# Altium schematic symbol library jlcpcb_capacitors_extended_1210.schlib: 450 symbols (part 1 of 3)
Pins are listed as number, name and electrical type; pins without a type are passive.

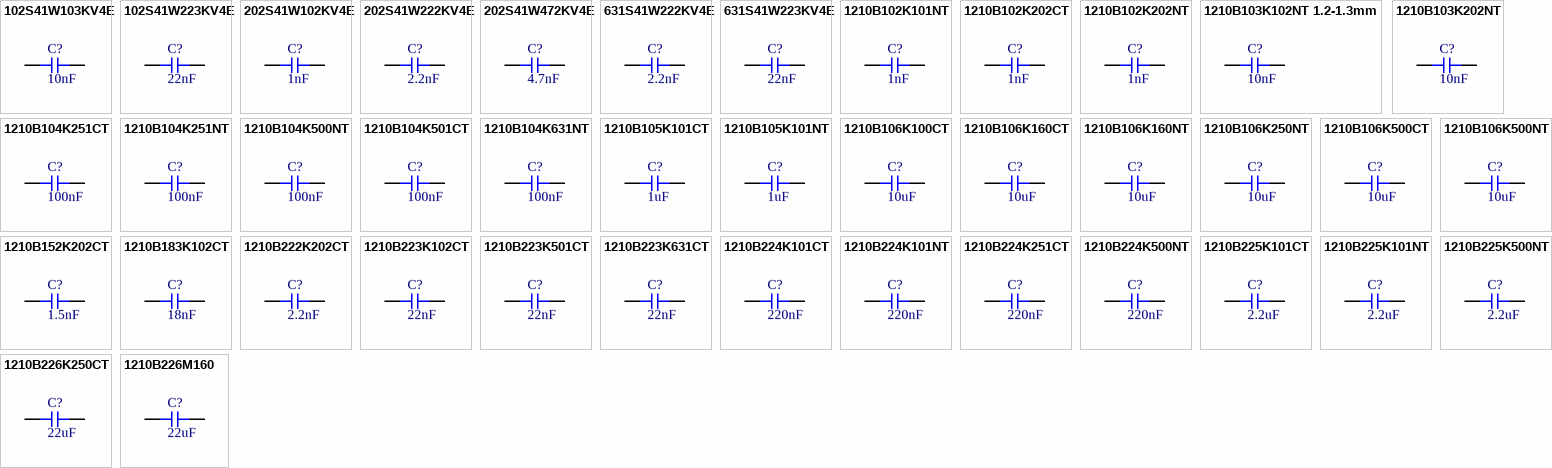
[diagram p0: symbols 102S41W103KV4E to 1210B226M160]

## 102S41W103KV4E
designator C?  Capacitance: 10nF  (hidden comment: *)
Capacitor, Ceramic (MLCC), 10nF, ±10%, 1kV, X7R, ±10%, SMD 1210; Manufacturer: Johanson Dielectrics; Manufacturer Part Number: 102S41W103KV4E
footprint CAP-1210 (1210 (3225M) Capacitor)
pins: 1, 2

## 102S41W223KV4E
designator C?  Capacitance: 22nF  (hidden comment: *)
Capacitor, Ceramic (MLCC), 22nF, ±10%, 1kV, X7R, ±10%, SMD 1210; Manufacturer: Johanson Dielectrics; Manufacturer Part Number: 102S41W223KV4E
footprint CAP-1210 (1210 (3225M) Capacitor)
pins: 1, 2

## 202S41W102KV4E
designator C?  Capacitance: 1nF  (hidden comment: *)
Capacitor, Ceramic (MLCC), 1nF, ±10%, 2kV, X7R, ±10%, SMD 1210; Manufacturer: Johanson Dielectrics; Manufacturer Part Number: 202S41W102KV4E
footprint CAP-1210 (1210 (3225M) Capacitor)
pins: 1, 2

## 202S41W222KV4E
designator C?  Capacitance: 2.2nF  (hidden comment: *)
Capacitor, Ceramic (MLCC), 2.2nF, ±10%, 2kV, X7R, ±10%, SMD 1210; Manufacturer: Johanson Dielectrics; Manufacturer Part Number: 202S41W222KV4E
footprint CAP-1210 (1210 (3225M) Capacitor)
pins: 1, 2

## 202S41W472KV4E
designator C?  Capacitance: 4.7nF  (hidden comment: *)
Capacitor, Ceramic (MLCC), 4.7nF, ±10%, 2kV, X7R, ±10%, SMD 1210; Manufacturer: Johanson Dielectrics; Manufacturer Part Number: 202S41W472KV4E
footprint CAP-1210 (1210 (3225M) Capacitor)
pins: 1, 2

## 631S41W222KV4E
designator C?  Capacitance: 2.2nF  (hidden comment: *)
Capacitor, Ceramic (MLCC), 2.2nF, ±10%, 630V, X7R, ±10%, SMD 1210; Manufacturer: Johanson Dielectrics; Manufacturer Part Number: 631S41W222KV4E
footprint CAP-1210 (1210 (3225M) Capacitor)
pins: 1, 2

## 631S41W223KV4E
designator C?  Capacitance: 22nF  (hidden comment: *)
Capacitor, Ceramic (MLCC), 22nF, ±10%, 630V, X7R, ±10%, SMD 1210; Manufacturer: Johanson Dielectrics; Manufacturer Part Number: 631S41W223KV4E
footprint CAP-1210 (1210 (3225M) Capacitor)
pins: 1, 2

## 1210B102K101NT
designator C?  Capacitance: 1nF  (hidden comment: *)
Capacitor, Ceramic (MLCC), 1nF, ±10%, 100V, X7R, ±10%, SMD 1210; Manufacturer: FH(Guangdong Fenghua Advanced Tech); Manufacturer Part Number: 1210B102K101NT
footprint CAP-1210 (1210 (3225M) Capacitor)
pins: 1, 2

## 1210B102K202CT
designator C?  Capacitance: 1nF  (hidden comment: *)
Capacitor, Ceramic (MLCC), 1nF, ±10%, 2kV, X7R, ±10%, SMD 1210; Manufacturer: Walsin Tech Corp; Manufacturer Part Number: 1210B102K202CT
footprint CAP-1210 (1210 (3225M) Capacitor)
pins: 1, 2

## 1210B102K202NT
designator C?  Capacitance: 1nF  (hidden comment: *)
Capacitor, Ceramic (MLCC), 1nF, ±10%, 2kV, ±10%, SMD 1210; Manufacturer: FH (Guangdong Fenghua Advanced Tech); Manufacturer Part Number: 1210B102K202NT
footprint CAP-1210 (1210 (3225M) Capacitor)
pins: 1, 2

## 1210B103K102NT 1.2-1.3mm
designator C?  Capacitance: 10nF  (hidden comment: *)
Capacitor, Ceramic (MLCC), 10nF, ±10%, 1kV, X7R, ±10%, SMD 1210; Manufacturer: FH(Guangdong Fenghua Advanced Tech); Manufacturer Part Number: 1210B103K102NT 1.2-1.3mm
footprint CAP-1210 (1210 (3225M) Capacitor)
pins: 1, 2

## 1210B103K202NT
designator C?  Capacitance: 10nF  (hidden comment: *)
Capacitor, Ceramic (MLCC), 10nF, ±10%, 2kV, X7R, ±10%, SMD 1210; Manufacturer: FH(Guangdong Fenghua Advanced Tech); Manufacturer Part Number: 1210B103K202NT
footprint CAP-1210 (1210 (3225M) Capacitor)
pins: 1, 2

## 1210B104K251CT
designator C?  Capacitance: 100nF  (hidden comment: *)
Capacitor, Ceramic (MLCC), 100nF, ±10%, 250V, X7R, ±10%, SMD 1210; Manufacturer: Walsin Tech Corp; Manufacturer Part Number: 1210B104K251CT
footprint CAP-1210 (1210 (3225M) Capacitor)
pins: 1, 2

## 1210B104K251NT
designator C?  Capacitance: 100nF  (hidden comment: *)
Capacitor, Ceramic (MLCC), 100nF, ±10%, 250V, X7R, ±10%, SMD 1210; Manufacturer: FH(Guangdong Fenghua Advanced Tech); Manufacturer Part Number: 1210B104K251NT
footprint CAP-1210 (1210 (3225M) Capacitor)
pins: 1, 2

## 1210B104K500NT
designator C?  Capacitance: 100nF  (hidden comment: *)
Capacitor, Ceramic (MLCC), 100nF, ±10%, 50V, X7R, ±10%, SMD 1210; Manufacturer: FH(Guangdong Fenghua Advanced Tech); Manufacturer Part Number: 1210B104K500NT
footprint CAP-1210 (1210 (3225M) Capacitor)
pins: 1, 2

## 1210B104K501CT
designator C?  Capacitance: 100nF  (hidden comment: *)
Capacitor, Ceramic (MLCC), 100nF, ±10%, 500V, X7R, ±10%, SMD 1210; Manufacturer: Walsin Tech Corp; Manufacturer Part Number: 1210B104K501CT
footprint CAP-1210 (1210 (3225M) Capacitor)
pins: 1, 2

## 1210B104K631NT
designator C?  Capacitance: 100nF  (hidden comment: *)
Capacitor, Ceramic (MLCC), 100nF, ±10%, 630V, ±10%, SMD 1210; Manufacturer: FH(Guangdong Fenghua Advanced Tech); Manufacturer Part Number: 1210B104K631NT
footprint CAP-1210 (1210 (3225M) Capacitor)
pins: 1, 2

## 1210B105K101CT
designator C?  Capacitance: 1uF  (hidden comment: *)
Capacitor, Ceramic (MLCC), 1uF, ±10%, 100V, X7R, ±10%, SMD 1210; Manufacturer: Walsin Tech Corp; Manufacturer Part Number: 1210B105K101CT
footprint CAP-1210 (1210 (3225M) Capacitor)
pins: 1, 2

## 1210B105K101NT
designator C?  Capacitance: 1uF  (hidden comment: *)
Capacitor, Ceramic (MLCC), 1uF, ±10%, 100V, X7R, ±10%, SMD 1210; Manufacturer: FH(Guangdong Fenghua Advanced Tech); Manufacturer Part Number: 1210B105K101NT
footprint CAP-1210 (1210 (3225M) Capacitor)
pins: 1, 2

## 1210B106K100CT
designator C?  Capacitance: 10uF  (hidden comment: *)
Capacitor, Ceramic (MLCC), 10uF, ±10%, 10V, X7R, ±10%, SMD 1210; Manufacturer: Walsin Tech Corp; Manufacturer Part Number: 1210B106K100CT
footprint CAP-1210 (1210 (3225M) Capacitor)
pins: 1, 2

## 1210B106K160CT
designator C?  Capacitance: 10uF  (hidden comment: *)
Capacitor, Ceramic (MLCC), 10uF, ±10%, 16V, X7R, ±10%, SMD 1210; Manufacturer: Walsin Tech Corp; Manufacturer Part Number: 1210B106K160CT
footprint CAP-1210 (1210 (3225M) Capacitor)
pins: 1, 2

## 1210B106K160NT
designator C?  Capacitance: 10uF  (hidden comment: *)
Capacitor, Ceramic (MLCC), 10uF, ±10%, 16V, X7R, ±10%, SMD 1210; Manufacturer: FH(Guangdong Fenghua Advanced Tech); Manufacturer Part Number: 1210B106K160NT
footprint CAP-1210 (1210 (3225M) Capacitor)
pins: 1, 2

## 1210B106K250NT
designator C?  Capacitance: 10uF  (hidden comment: *)
Capacitor, Ceramic (MLCC), 10uF, ±10%, 25V, X7R, ±10%, SMD 1210; Manufacturer: FH(Guangdong Fenghua Advanced Tech); Manufacturer Part Number: 1210B106K250NT
footprint CAP-1210 (1210 (3225M) Capacitor)
pins: 1, 2

## 1210B106K500CT
designator C?  Capacitance: 10uF  (hidden comment: *)
Capacitor, Ceramic (MLCC), 10uF, ±10%, 50V, X7R, ±10%, SMD 1210; Manufacturer: Walsin Tech Corp; Manufacturer Part Number: 1210B106K500CT
footprint CAP-1210 (1210 (3225M) Capacitor)
pins: 1, 2

## 1210B106K500NT
designator C?  Capacitance: 10uF  (hidden comment: *)
Capacitor, Ceramic (MLCC), 10uF, ±10%, 50V, X7R, ±10%, SMD 1210; Manufacturer: FH(Guangdong Fenghua Advanced Tech); Manufacturer Part Number: 1210B106K500NT
footprint CAP-1210 (1210 (3225M) Capacitor)
pins: 1, 2

## 1210B152K202CT
designator C?  Capacitance: 1.5nF  (hidden comment: *)
Capacitor, Ceramic (MLCC), 1.5nF, ±10%, 2kV, X7R, ±10%, SMD 1210; Manufacturer: Walsin Tech Corp; Manufacturer Part Number: 1210B152K202CT
footprint CAP-1210 (1210 (3225M) Capacitor)
pins: 1, 2

## 1210B183K102CT
designator C?  Capacitance: 18nF  (hidden comment: *)
Capacitor, Ceramic (MLCC), 18nF, ±10%, 1kV, X7R, ±10%, SMD 1210; Manufacturer: Walsin Tech Corp; Manufacturer Part Number: 1210B183K102CT
footprint CAP-1210 (1210 (3225M) Capacitor)
pins: 1, 2

## 1210B222K202CT
designator C?  Capacitance: 2.2nF  (hidden comment: *)
Capacitor, Ceramic (MLCC), 2.2nF, ±10%, 2kV, X7R, ±10%, SMD 1210; Manufacturer: Walsin Tech Corp; Manufacturer Part Number: 1210B222K202CT
footprint CAP-1210 (1210 (3225M) Capacitor)
pins: 1, 2

## 1210B223K102CT
designator C?  Capacitance: 22nF  (hidden comment: *)
Capacitor, Ceramic (MLCC), 22nF, ±10%, 1kV, X7R, ±10%, SMD 1210; Manufacturer: Walsin Tech Corp; Manufacturer Part Number: 1210B223K102CT
footprint CAP-1210 (1210 (3225M) Capacitor)
pins: 1, 2

## 1210B223K501CT
designator C?  Capacitance: 22nF  (hidden comment: *)
Capacitor, Ceramic (MLCC), 22nF, ±10%, 500V, X7R, ±10%, SMD 1210; Manufacturer: Walsin Tech Corp; Manufacturer Part Number: 1210B223K501CT
footprint CAP-1210 (1210 (3225M) Capacitor)
pins: 1, 2

## 1210B223K631CT
designator C?  Capacitance: 22nF  (hidden comment: *)
Capacitor, Ceramic (MLCC), 22nF, ±10%, 630V, X7R, ±10%, SMD 1210; Manufacturer: Walsin Tech Corp; Manufacturer Part Number: 1210B223K631CT
footprint CAP-1210 (1210 (3225M) Capacitor)
pins: 1, 2

## 1210B224K101CT
designator C?  Capacitance: 220nF  (hidden comment: *)
Capacitor, Ceramic (MLCC), 220nF, ±10%, 100V, X7R, ±10%, SMD 1210; Manufacturer: Walsin Tech Corp; Manufacturer Part Number: 1210B224K101CT
footprint CAP-1210 (1210 (3225M) Capacitor)
pins: 1, 2

## 1210B224K101NT
designator C?  Capacitance: 220nF  (hidden comment: *)
Capacitor, Ceramic (MLCC), 220nF, ±10%, 100V, X7R, ±10%, SMD 1210; Manufacturer: FH(Guangdong Fenghua Advanced Tech); Manufacturer Part Number: 1210B224K101NT
footprint CAP-1210 (1210 (3225M) Capacitor)
pins: 1, 2

## 1210B224K251CT
designator C?  Capacitance: 220nF  (hidden comment: *)
Capacitor, Ceramic (MLCC), 220nF, ±10%, 250V, X7R, ±10%, SMD 1210; Manufacturer: Walsin Tech Corp; Manufacturer Part Number: 1210B224K251CT
footprint CAP-1210 (1210 (3225M) Capacitor)
pins: 1, 2

## 1210B224K500NT
designator C?  Capacitance: 220nF  (hidden comment: *)
Capacitor, Ceramic (MLCC), 220nF, ±10%, 50V, ±10%, SMD 1210; Manufacturer: FH(Guangdong Fenghua Advanced Tech); Manufacturer Part Number: 1210B224K500NT
footprint CAP-1210 (1210 (3225M) Capacitor)
pins: 1, 2

## 1210B225K101CT
designator C?  Capacitance: 2.2uF  (hidden comment: *)
Capacitor, Ceramic (MLCC), 2.2uF, ±10%, 100V, X7R, ±10%, SMD 1210; Manufacturer: Walsin Tech Corp; Manufacturer Part Number: 1210B225K101CT
footprint CAP-1210 (1210 (3225M) Capacitor)
pins: 1, 2

## 1210B225K101NT
designator C?  Capacitance: 2.2uF  (hidden comment: *)
Capacitor, Ceramic (MLCC), 2.2uF, ±10%, 100V, X7R, ±10%, SMD 1210; Manufacturer: FH(Guangdong Fenghua Advanced Tech); Manufacturer Part Number: 1210B225K101NT
footprint CAP-1210 (1210 (3225M) Capacitor)
pins: 1, 2

## 1210B225K500NT
designator C?  Capacitance: 2.2uF  (hidden comment: *)
Capacitor, Ceramic (MLCC), 2.2uF, ±10%, 50V, X7R, ±10%, SMD 1210; Manufacturer: FH(Guangdong Fenghua Advanced Tech); Manufacturer Part Number: 1210B225K500NT
footprint CAP-1210 (1210 (3225M) Capacitor)
pins: 1, 2

## 1210B226K250CT
designator C?  Capacitance: 22uF  (hidden comment: *)
Capacitor, Ceramic (MLCC), 22uF, ±10%, 25V, X7R, ±10%, SMD 1210; Manufacturer: Walsin Tech Corp; Manufacturer Part Number: 1210B226K250CT
footprint CAP-1210 (1210 (3225M) Capacitor)
pins: 1, 2

## 1210B226M160
designator C?  Capacitance: 22uF  (hidden comment: *)
Capacitor, Ceramic (MLCC), 22uF, ±20%, 16V, X7R, ±20%, SMD 1210; Manufacturer: Walsin Tech Corp; Manufacturer Part Number: 1210B226M160
footprint CAP-1210 (1210 (3225M) Capacitor)
pins: 1, 2

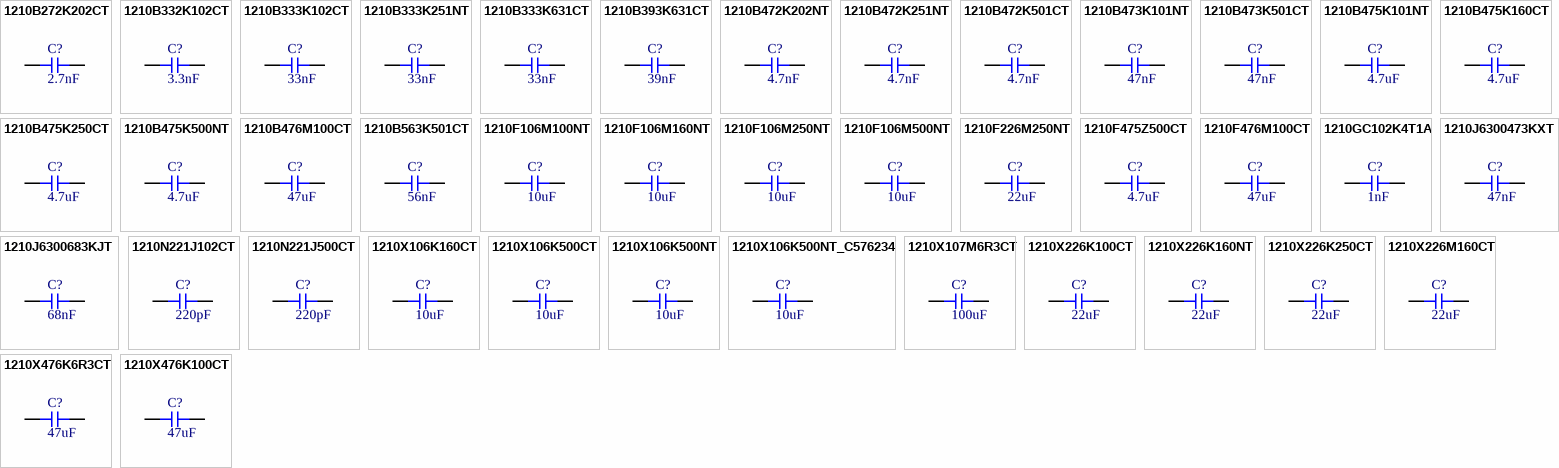
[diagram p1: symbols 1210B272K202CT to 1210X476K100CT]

## 1210B272K202CT
designator C?  Capacitance: 2.7nF  (hidden comment: *)
Capacitor, Ceramic (MLCC), 2.7nF, ±10%, 2kV, X7R, ±10%, SMD 1210; Manufacturer: Walsin Tech Corp; Manufacturer Part Number: 1210B272K202CT
footprint CAP-1210 (1210 (3225M) Capacitor)
pins: 1, 2

## 1210B332K102CT
designator C?  Capacitance: 3.3nF  (hidden comment: *)
Capacitor, Ceramic (MLCC), 3.3nF, ±10%, 1kV, X7R, ±10%, SMD 1210; Manufacturer: Walsin Tech Corp; Manufacturer Part Number: 1210B332K102CT
footprint CAP-1210 (1210 (3225M) Capacitor)
pins: 1, 2

## 1210B333K102CT
designator C?  Capacitance: 33nF  (hidden comment: *)
Capacitor, Ceramic (MLCC), 33nF, ±10%, 1kV, X7R, ±10%, SMD 1210; Manufacturer: Walsin Tech Corp; Manufacturer Part Number: 1210B333K102CT
footprint CAP-1210 (1210 (3225M) Capacitor)
pins: 1, 2

## 1210B333K251NT
designator C?  Capacitance: 33nF  (hidden comment: *)
Capacitor, Ceramic (MLCC), 33nF, ±10%, 250V, ±10%, SMD 1210; Manufacturer: FH(Guangdong Fenghua Advanced Tech); Manufacturer Part Number: 1210B333K251NT
footprint CAP-1210 (1210 (3225M) Capacitor)
pins: 1, 2

## 1210B333K631CT
designator C?  Capacitance: 33nF  (hidden comment: *)
Capacitor, Ceramic (MLCC), 33nF, ±10%, 630V, X7R, ±10%, SMD 1210; Manufacturer: Walsin Tech Corp; Manufacturer Part Number: 1210B333K631CT
footprint CAP-1210 (1210 (3225M) Capacitor)
pins: 1, 2

## 1210B393K631CT
designator C?  Capacitance: 39nF  (hidden comment: *)
Capacitor, Ceramic (MLCC), 39nF, ±10%, 630V, X7R, ±10%, SMD 1210; Manufacturer: Walsin Tech Corp; Manufacturer Part Number: 1210B393K631CT
footprint CAP-1210 (1210 (3225M) Capacitor)
pins: 1, 2

## 1210B472K202NT
designator C?  Capacitance: 4.7nF  (hidden comment: *)
Capacitor, Ceramic (MLCC), 4.7nF, ±10%, 2kV, X7R, ±10%, SMD 1210; Manufacturer: FH(Guangdong Fenghua Advanced Tech); Manufacturer Part Number: 1210B472K202NT
footprint CAP-1210 (1210 (3225M) Capacitor)
pins: 1, 2

## 1210B472K251NT
designator C?  Capacitance: 4.7nF  (hidden comment: *)
Capacitor, Ceramic (MLCC), 4.7nF, ±10%, 250V, X7R, ±10%, SMD 1210; Manufacturer: FH(Guangdong Fenghua Advanced Tech); Manufacturer Part Number: 1210B472K251NT
footprint CAP-1210 (1210 (3225M) Capacitor)
pins: 1, 2

## 1210B472K501CT
designator C?  Capacitance: 4.7nF  (hidden comment: *)
Capacitor, Ceramic (MLCC), 4.7nF, ±10%, 500V, X7R, ±10%, SMD 1210; Manufacturer: Walsin Tech Corp; Manufacturer Part Number: 1210B472K501CT
footprint CAP-1210 (1210 (3225M) Capacitor)
pins: 1, 2

## 1210B473K101NT
designator C?  Capacitance: 47nF  (hidden comment: *)
Capacitor, Ceramic (MLCC), 47nF, ±10%, 100V, X7R, ±10%, SMD 1210; Manufacturer: FH(Guangdong Fenghua Advanced Tech); Manufacturer Part Number: 1210B473K101NT
footprint CAP-1210 (1210 (3225M) Capacitor)
pins: 1, 2

## 1210B473K501CT
designator C?  Capacitance: 47nF  (hidden comment: *)
Capacitor, Ceramic (MLCC), 47nF, ±10%, 500V, X7R, ±10%, SMD 1210; Manufacturer: Walsin Tech Corp; Manufacturer Part Number: 1210B473K501CT
footprint CAP-1210 (1210 (3225M) Capacitor)
pins: 1, 2

## 1210B475K101NT
designator C?  Capacitance: 4.7uF  (hidden comment: *)
Capacitor, Ceramic (MLCC), 4.7uF, ±10%, 100V, ±10%, SMD 1210; Manufacturer: FH(Guangdong Fenghua Advanced Tech); Manufacturer Part Number: 1210B475K101NT
footprint CAP-1210 (1210 (3225M) Capacitor)
pins: 1, 2

## 1210B475K160CT
designator C?  Capacitance: 4.7uF  (hidden comment: *)
Capacitor, Ceramic (MLCC), 4.7uF, ±10%, 16V, X7R, ±10%, SMD 1210; Manufacturer: Walsin Tech Corp; Manufacturer Part Number: 1210B475K160CT
footprint CAP-1210 (1210 (3225M) Capacitor)
pins: 1, 2

## 1210B475K250CT
designator C?  Capacitance: 4.7uF  (hidden comment: *)
Capacitor, Ceramic (MLCC), 4.7uF, ±10%, 25V, X7R, ±10%, SMD 1210; Manufacturer: Walsin Tech Corp; Manufacturer Part Number: 1210B475K250CT
footprint CAP-1210 (1210 (3225M) Capacitor)
pins: 1, 2

## 1210B475K500NT
designator C?  Capacitance: 4.7uF  (hidden comment: *)
Capacitor, Ceramic (MLCC), 4.7uF, ±10%, 50V, X7R, ±10%, SMD 1210; Manufacturer: FH(Guangdong Fenghua Advanced Tech); Manufacturer Part Number: 1210B475K500NT
footprint CAP-1210 (1210 (3225M) Capacitor)
pins: 1, 2

## 1210B476M100CT
designator C?  Capacitance: 47uF  (hidden comment: *)
Capacitor, Ceramic (MLCC), 47uF, ±20%, 10V, X7R, ±20%, SMD 1210; Manufacturer: Walsin Tech Corp; Manufacturer Part Number: 1210B476M100CT
footprint CAP-1210 (1210 (3225M) Capacitor)
pins: 1, 2

## 1210B563K501CT
designator C?  Capacitance: 56nF  (hidden comment: *)
Capacitor, Ceramic (MLCC), 56nF, ±10%, 500V, X7R, ±10%, SMD 1210; Manufacturer: Walsin Tech Corp; Manufacturer Part Number: 1210B563K501CT
footprint CAP-1210 (1210 (3225M) Capacitor)
pins: 1, 2

## 1210F106M100NT
designator C?  Capacitance: 10uF  (hidden comment: *)
Capacitor, Ceramic (MLCC), 10uF, ±20%, 10V, ±20%, SMD 1210; Manufacturer: FH(Guangdong Fenghua Advanced Tech); Manufacturer Part Number: 1210F106M100NT
footprint CAP-1210 (1210 (3225M) Capacitor)
pins: 1, 2

## 1210F106M160NT
designator C?  Capacitance: 10uF  (hidden comment: *)
Capacitor, Ceramic (MLCC), 10uF, ±20%, 16V, Y5V, ±20%, SMD 1210; Manufacturer: FH(Guangdong Fenghua Advanced Tech); Manufacturer Part Number: 1210F106M160NT
footprint CAP-1210 (1210 (3225M) Capacitor)
pins: 1, 2

## 1210F106M250NT
designator C?  Capacitance: 10uF  (hidden comment: *)
Capacitor, Ceramic (MLCC), 10uF, ±20%, 25V, Y5V, ±20%, SMD 1210; Manufacturer: FH(Guangdong Fenghua Advanced Tech); Manufacturer Part Number: 1210F106M250NT
footprint CAP-1210 (1210 (3225M) Capacitor)
pins: 1, 2

## 1210F106M500NT
designator C?  Capacitance: 10uF  (hidden comment: *)
Capacitor, Ceramic (MLCC), 10uF, ±20%, 50V, Y5V, ±20%, SMD 1210; Manufacturer: FH(Guangdong Fenghua Advanced Tech); Manufacturer Part Number: 1210F106M500NT
footprint CAP-1210 (1210 (3225M) Capacitor)
pins: 1, 2

## 1210F226M250NT
designator C?  Capacitance: 22uF  (hidden comment: *)
Capacitor, Ceramic (MLCC), 22uF, ±20%, 25V, Y5V, ±20%, SMD 1210; Manufacturer: FH(Guangdong Fenghua Advanced Tech); Manufacturer Part Number: 1210F226M250NT
footprint CAP-1210 (1210 (3225M) Capacitor)
pins: 1, 2

## 1210F475Z500CT
designator C?  Capacitance: 4.7uF  (hidden comment: *)
Capacitor, Ceramic (MLCC), 4.7uF, 50V, Y5V, SMD 1210; Manufacturer: Walsin Tech Corp; Manufacturer Part Number: 1210F475Z500CT; Temperature Rating: -20%~+80%
footprint CAP-1210 (1210 (3225M) Capacitor)
pins: 1, 2

## 1210F476M100CT
designator C?  Capacitance: 47uF  (hidden comment: *)
Capacitor, Ceramic (MLCC), 47uF, ±20%, 10V, Y5V, ±20%, SMD 1210; Manufacturer: Walsin Tech Corp; Manufacturer Part Number: 1210F476M100CT
footprint CAP-1210 (1210 (3225M) Capacitor)
pins: 1, 2

## 1210GC102K4T1A
designator C?  Capacitance: 1nF  (hidden comment: *)
Capacitor, Ceramic (MLCC), 1nF, ±10%, 2kV, X7R, ±10%, SMD 1210; Manufacturer: AVX; Manufacturer Part Number: 1210GC102K4T1A
footprint CAP-1210 (1210 (3225M) Capacitor)
pins: 1, 2

## 1210J6300473KXT
designator C?  Capacitance: 47nF  (hidden comment: *)
Capacitor, Ceramic (MLCC), 47nF, ±10%, 630V, X7R, ±10%, SMD 1210; Manufacturer: Knowles; Manufacturer Part Number: 1210J6300473KXT
footprint CAP-1210 (1210 (3225M) Capacitor)
pins: 1, 2

## 1210J6300683KJT
designator C?  Capacitance: 68nF  (hidden comment: *)
Capacitor, Ceramic (MLCC), 68nF, ±10%, 630V, X7R, ±10%, SMD 1210; Manufacturer: Knowles; Manufacturer Part Number: 1210J6300683KJT
footprint CAP-1210 (1210 (3225M) Capacitor)
pins: 1, 2

## 1210N221J102CT
designator C?  Capacitance: 220pF  (hidden comment: *)
Capacitor, Ceramic (MLCC), 220pF, ±5%, 1kV, NP0, ±5%, SMD 1210; Manufacturer: Walsin Tech Corp; Manufacturer Part Number: 1210N221J102CT
footprint CAP-1210 (1210 (3225M) Capacitor)
pins: 1, 2

## 1210N221J500CT
designator C?  Capacitance: 220pF  (hidden comment: *)
Capacitor, Ceramic (MLCC), 220pF, ±5%, 50V, NP0, ±5%, SMD 1210; Manufacturer: Walsin Tech Corp; Manufacturer Part Number: 1210N221J500CT
footprint CAP-1210 (1210 (3225M) Capacitor)
pins: 1, 2

## 1210X106K160CT
designator C?  Capacitance: 10uF  (hidden comment: *)
Capacitor, Ceramic (MLCC), 10uF, ±10%, 16V, X5R, ±10%, SMD 1210; Manufacturer: Walsin Tech Corp; Manufacturer Part Number: 1210X106K160CT
footprint CAP-1210 (1210 (3225M) Capacitor)
pins: 1, 2

## 1210X106K500CT
designator C?  Capacitance: 10uF  (hidden comment: *)
Capacitor, Ceramic (MLCC), 10uF, ±10%, 50V, X5R, ±10%, SMD 1210; Manufacturer: Walsin Tech Corp; Manufacturer Part Number: 1210X106K500CT
footprint CAP-1210 (1210 (3225M) Capacitor)
pins: 1, 2

## 1210X106K500NT
designator C?  Capacitance: 10uF  (hidden comment: *)
Capacitor, Ceramic (MLCC), 10uF, ±10%, 50V, X5R, ±10%, SMD 1210; Manufacturer: FH(Guangdong Fenghua Advanced Tech); Manufacturer Part Number: 1210X106K500NT
footprint CAP-1210 (1210 (3225M) Capacitor)
pins: 1, 2

## 1210X106K500NT_C576234
designator C?  Capacitance: 10uF  (hidden comment: *)
Capacitor, Ceramic (MLCC), 10uF, ±10%, 50V, X5R, ±10%, SMD 1210; Manufacturer: FH(Guangdong Fenghua Advanced Tech); Manufacturer Part Number: 1210X106K500NT
footprint CAP-1210 (1210 (3225M) Capacitor)
pins: 1, 2

## 1210X107M6R3CT
designator C?  Capacitance: 100uF  (hidden comment: *)
Capacitor, Ceramic (MLCC), 100uF, ±20%, 6.3V, X5R, ±20%, SMD 1210; Manufacturer: Walsin Tech Corp; Manufacturer Part Number: 1210X107M6R3CT
footprint CAP-1210 (1210 (3225M) Capacitor)
pins: 1, 2

## 1210X226K100CT
designator C?  Capacitance: 22uF  (hidden comment: *)
Capacitor, Ceramic (MLCC), 22uF, ±10%, 10V, X5R, ±10%, SMD 1210; Manufacturer: Walsin Tech Corp; Manufacturer Part Number: 1210X226K100CT
footprint CAP-1210 (1210 (3225M) Capacitor)
pins: 1, 2

## 1210X226K160NT
designator C?  Capacitance: 22uF  (hidden comment: *)
Capacitor, Ceramic (MLCC), 22uF, ±10%, 16V, X5R, ±10%, SMD 1210; Manufacturer: FH(Guangdong Fenghua Advanced Tech); Manufacturer Part Number: 1210X226K160NT
footprint CAP-1210 (1210 (3225M) Capacitor)
pins: 1, 2

## 1210X226K250CT
designator C?  Capacitance: 22uF  (hidden comment: *)
Capacitor, Ceramic (MLCC), 22uF, ±10%, 25V, X5R, ±10%, SMD 1210; Manufacturer: Walsin Tech Corp; Manufacturer Part Number: 1210X226K250CT
footprint CAP-1210 (1210 (3225M) Capacitor)
pins: 1, 2

## 1210X226M160CT
designator C?  Capacitance: 22uF  (hidden comment: *)
Capacitor, Ceramic (MLCC), 22uF, ±20%, 16V, X5R, ±20%, SMD 1210; Manufacturer: Walsin Tech Corp; Manufacturer Part Number: 1210X226M160CT
footprint CAP-1210 (1210 (3225M) Capacitor)
pins: 1, 2

## 1210X476K6R3CT
designator C?  Capacitance: 47uF  (hidden comment: *)
Capacitor, Ceramic (MLCC), 47uF, ±10%, 6.3V, X5R, ±10%, SMD 1210; Manufacturer: Walsin Tech Corp; Manufacturer Part Number: 1210X476K6R3CT
footprint CAP-1210 (1210 (3225M) Capacitor)
pins: 1, 2

## 1210X476K100CT
designator C?  Capacitance: 47uF  (hidden comment: *)
Capacitor, Ceramic (MLCC), 47uF, ±10%, 10V, X5R, ±10%, SMD 1210; Manufacturer: Walsin Tech Corp; Manufacturer Part Number: 1210X476K100CT
footprint CAP-1210 (1210 (3225M) Capacitor)
pins: 1, 2

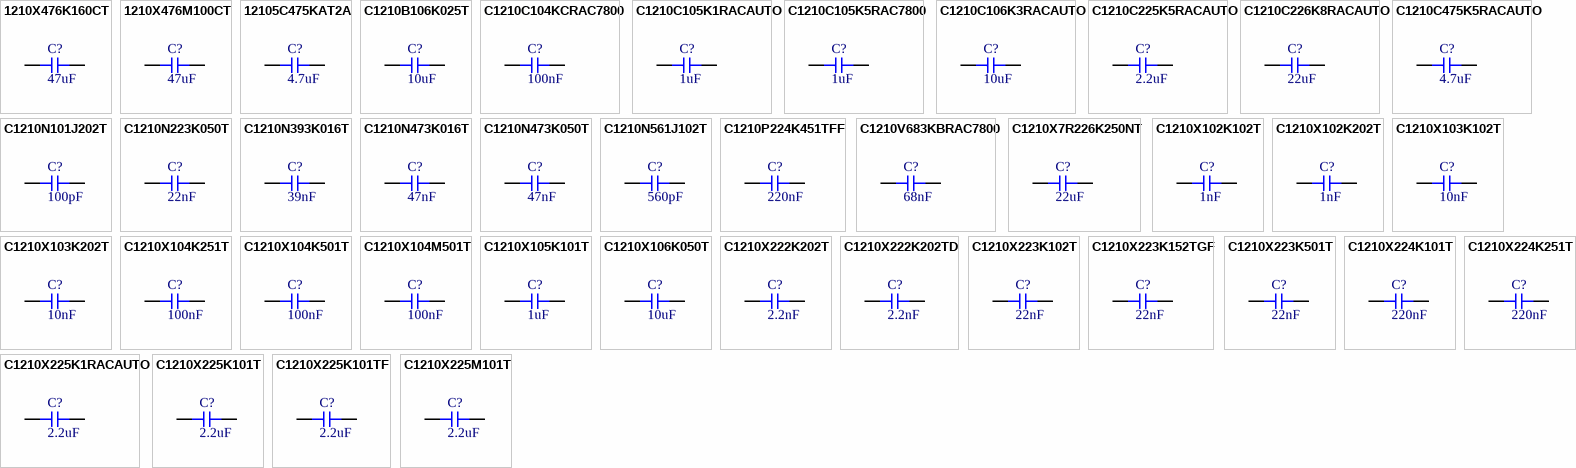
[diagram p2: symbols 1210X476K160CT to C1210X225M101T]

## 1210X476K160CT
designator C?  Capacitance: 47uF  (hidden comment: *)
Capacitor, Ceramic (MLCC), 47uF, ±10%, 16V, X5R, ±10%, SMD 1210; Manufacturer: Walsin Tech Corp; Manufacturer Part Number: 1210X476K160CT
footprint CAP-1210 (1210 (3225M) Capacitor)
pins: 1, 2

## 1210X476M100CT
designator C?  Capacitance: 47uF  (hidden comment: *)
Capacitor, Ceramic (MLCC), 47uF, ±20%, 10V, X5R, ±20%, SMD 1210; Manufacturer: Walsin Tech Corp; Manufacturer Part Number: 1210X476M100CT
footprint CAP-1210 (1210 (3225M) Capacitor)
pins: 1, 2

## 12105C475KAT2A
designator C?  Capacitance: 4.7uF  (hidden comment: *)
Capacitor, Ceramic (MLCC), 4.7uF, ±10%, 50V, X7R, ±10%, SMD 1210; Manufacturer: AVX; Manufacturer Part Number: 12105C475KAT2A
footprint CAP-1210 (1210 (3225M) Capacitor)
pins: 1, 2

## C1210B106K025T
designator C?  Capacitance: 10uF  (hidden comment: *)
Capacitor, Ceramic (MLCC), 10uF, ±10%, 25V, X5R, ±10%, SMD 1210; Manufacturer: IHHEC(HOLY STONE ENTERPRISE CO., LTD); Manufacturer Part Number: C1210B106K025T
footprint CAP-1210 (1210 (3225M) Capacitor)
pins: 1, 2

## C1210C104KCRAC7800
designator C?  Capacitance: 100nF  (hidden comment: *)
Capacitor, Ceramic (MLCC), 100nF, ±10%, 500V, X7R, ±10%, SMD 1210; Manufacturer: KEMET; Manufacturer Part Number: C1210C104KCRAC7800
footprint CAP-1210 (1210 (3225M) Capacitor)
pins: 1, 2

## C1210C105K1RACAUTO
designator C?  Capacitance: 1uF  (hidden comment: *)
Capacitor, Ceramic (MLCC), 1uF, ±10%, 100V, X7R, ±10%, SMD 1210; Manufacturer: KEMET; Manufacturer Part Number: C1210C105K1RACAUTO
footprint CAP-1210 (1210 (3225M) Capacitor)
pins: 1, 2

## C1210C105K5RAC7800
designator C?  Capacitance: 1uF  (hidden comment: *)
Capacitor, Ceramic (MLCC), 1uF, ±10%, 50V, X7R, ±10%, SMD 1210; Manufacturer: KEMET; Manufacturer Part Number: C1210C105K5RAC7800
footprint CAP-1210 (1210 (3225M) Capacitor)
pins: 1, 2

## C1210C106K3RACAUTO
designator C?  Capacitance: 10uF  (hidden comment: *)
Capacitor, Ceramic (MLCC), 10uF, ±10%, 25V, X7R, ±10%, SMD 1210; Manufacturer: KEMET; Manufacturer Part Number: C1210C106K3RACAUTO
footprint CAP-1210 (1210 (3225M) Capacitor)
pins: 1, 2

## C1210C225K5RACAUTO
designator C?  Capacitance: 2.2uF  (hidden comment: *)
Capacitor, Ceramic (MLCC), 2.2uF, ±10%, 50V, X7R, ±10%, SMD 1210; Manufacturer: KEMET; Manufacturer Part Number: C1210C225K5RACAUTO
footprint CAP-1210 (1210 (3225M) Capacitor)
pins: 1, 2

## C1210C226K8RACAUTO
designator C?  Capacitance: 22uF  (hidden comment: *)
Capacitor, Ceramic (MLCC), 22uF, ±10%, 10V, X7R, ±10%, SMD 1210; Manufacturer: KEMET; Manufacturer Part Number: C1210C226K8RACAUTO
footprint CAP-1210 (1210 (3225M) Capacitor)
pins: 1, 2

## C1210C475K5RACAUTO
designator C?  Capacitance: 4.7uF  (hidden comment: *)
Capacitor, Ceramic (MLCC), 4.7uF, ±10%, 50V, X7R, ±10%, SMD 1210; Manufacturer: KEMET; Manufacturer Part Number: C1210C475K5RACAUTO
footprint CAP-1210 (1210 (3225M) Capacitor)
pins: 1, 2

## C1210N101J202T
designator C?  Capacitance: 100pF  (hidden comment: *)
Capacitor, Ceramic (MLCC), 100pF, ±5%, 2kV, C0G, ±5%, SMD 1210; Manufacturer: IHHEC(HOLY STONE ENTERPRISE CO., LTD); Manufacturer Part Number: C1210N101J202T
footprint CAP-1210 (1210 (3225M) Capacitor)
pins: 1, 2

## C1210N223K050T
designator C?  Capacitance: 22nF  (hidden comment: *)
Capacitor, Ceramic (MLCC), 22nF, ±10%, 50V, NP0, ±10%, SMD 1210; Manufacturer: IHHEC(HOLY STONE ENTERPRISE CO., LTD); Manufacturer Part Number: C1210N223K050T
footprint CAP-1210 (1210 (3225M) Capacitor)
pins: 1, 2

## C1210N393K016T
designator C?  Capacitance: 39nF  (hidden comment: *)
Capacitor, Ceramic (MLCC), 39nF, ±10%, 16V, NP0, ±10%, SMD 1210; Manufacturer: IHHEC(HOLY STONE ENTERPRISE CO., LTD); Manufacturer Part Number: C1210N393K016T
footprint CAP-1210 (1210 (3225M) Capacitor)
pins: 1, 2

## C1210N473K016T
designator C?  Capacitance: 47nF  (hidden comment: *)
Capacitor, Ceramic (MLCC), 47nF, ±10%, 16V, NP0, ±10%, SMD 1210; Manufacturer: IHHEC(HOLY STONE ENTERPRISE CO., LTD); Manufacturer Part Number: C1210N473K016T
footprint CAP-1210 (1210 (3225M) Capacitor)
pins: 1, 2

## C1210N473K050T
designator C?  Capacitance: 47nF  (hidden comment: *)
Capacitor, Ceramic (MLCC), 47nF, ±10%, 50V, NP0, ±10%, SMD 1210; Manufacturer: IHHEC(HOLY STONE ENTERPRISE CO., LTD); Manufacturer Part Number: C1210N473K050T
footprint CAP-1210 (1210 (3225M) Capacitor)
pins: 1, 2

## C1210N561J102T
designator C?  Capacitance: 560pF  (hidden comment: *)
Capacitor, Ceramic (MLCC), 560pF, ±5%, 1kV, C0G, ±5%, SMD 1210; Manufacturer: IHHEC(HOLY STONE ENTERPRISE CO., LTD); Manufacturer Part Number: C1210N561J102T
footprint CAP-1210 (1210 (3225M) Capacitor)
pins: 1, 2

## C1210P224K451TFF
designator C?  Capacitance: 220nF  (hidden comment: *)
Capacitor, Ceramic (MLCC), 220nF, ±10%, 450V, ±10%, SMD 1210; Manufacturer: IHHEC(HOLY STONE ENTERPRISE CO., LTD); Manufacturer Part Number: C1210P224K451TFF
footprint CAP-1210 (1210 (3225M) Capacitor)
pins: 1, 2

## C1210V683KBRAC7800
designator C?  Capacitance: 68nF  (hidden comment: *)
Capacitor, Ceramic (MLCC), 68nF, ±10%, 630V, X7R, ±10%, SMD 1210; Manufacturer: KEMET; Manufacturer Part Number: C1210V683KBRAC7800
footprint CAP-1210 (1210 (3225M) Capacitor)
pins: 1, 2

## C1210X7R226K250NT
designator C?  Capacitance: 22uF  (hidden comment: *)
Capacitor, Ceramic (MLCC), 22uF, ±10%, 25V, ±10%, SMD 1210; Manufacturer: SANYEAR; Manufacturer Part Number: C1210X7R226K250NT
footprint CAP-1210 (1210 (3225M) Capacitor)
pins: 1, 2

## C1210X102K102T
designator C?  Capacitance: 1nF  (hidden comment: *)
Capacitor, Ceramic (MLCC), 1nF, ±10%, 1kV, X7R, ±10%, SMD 1210; Manufacturer: IHHEC(HOLY STONE ENTERPRISE CO., LTD); Manufacturer Part Number: C1210X102K102T
footprint CAP-1210 (1210 (3225M) Capacitor)
pins: 1, 2

## C1210X102K202T
designator C?  Capacitance: 1nF  (hidden comment: *)
Capacitor, Ceramic (MLCC), 1nF, ±10%, 2kV, X7R, ±10%, SMD 1210; Manufacturer: IHHEC(HOLY STONE ENTERPRISE CO., LTD); Manufacturer Part Number: C1210X102K202T
footprint CAP-1210 (1210 (3225M) Capacitor)
pins: 1, 2

## C1210X103K102T
designator C?  Capacitance: 10nF  (hidden comment: *)
Capacitor, Ceramic (MLCC), 10nF, ±10%, 1kV, X7R, ±10%, SMD 1210; Manufacturer: IHHEC(HOLY STONE ENTERPRISE CO., LTD); Manufacturer Part Number: C1210X103K102T
footprint CAP-1210 (1210 (3225M) Capacitor)
pins: 1, 2

## C1210X103K202T
designator C?  Capacitance: 10nF  (hidden comment: *)
Capacitor, Ceramic (MLCC), 10nF, ±10%, 2kV, X7R, ±10%, SMD 1210; Manufacturer: IHHEC(HOLY STONE ENTERPRISE CO., LTD); Manufacturer Part Number: C1210X103K202T
footprint CAP-1210 (1210 (3225M) Capacitor)
pins: 1, 2

## C1210X104K251T
designator C?  Capacitance: 100nF  (hidden comment: *)
Capacitor, Ceramic (MLCC), 100nF, ±10%, 250V, X7R, ±10%, SMD 1210; Manufacturer: IHHEC(HOLY STONE ENTERPRISE CO., LTD); Manufacturer Part Number: C1210X104K251T
footprint CAP-1210 (1210 (3225M) Capacitor)
pins: 1, 2

## C1210X104K501T
designator C?  Capacitance: 100nF  (hidden comment: *)
Capacitor, Ceramic (MLCC), 100nF, ±10%, 500V, X7R, ±10%, SMD 1210; Manufacturer: IHHEC(HOLY STONE ENTERPRISE CO., LTD); Manufacturer Part Number: C1210X104K501T
footprint CAP-1210 (1210 (3225M) Capacitor)
pins: 1, 2

## C1210X104M501T
designator C?  Capacitance: 100nF  (hidden comment: *)
Capacitor, Ceramic (MLCC), 100nF, ±20%, 500V, X7R, ±20%, SMD 1210; Manufacturer: IHHEC(HOLY STONE ENTERPRISE CO., LTD); Manufacturer Part Number: C1210X104M501T
footprint CAP-1210 (1210 (3225M) Capacitor)
pins: 1, 2

## C1210X105K101T
designator C?  Capacitance: 1uF  (hidden comment: *)
Capacitor, Ceramic (MLCC), 1uF, ±10%, 100V, X7R, ±10%, SMD 1210; Manufacturer: IHHEC(HOLY STONE ENTERPRISE CO., LTD); Manufacturer Part Number: C1210X105K101T
footprint CAP-1210 (1210 (3225M) Capacitor)
pins: 1, 2

## C1210X106K050T
designator C?  Capacitance: 10uF  (hidden comment: *)
Capacitor, Ceramic (MLCC), 10uF, ±10%, 50V, X7R, ±10%, SMD 1210; Manufacturer: IHHEC(HOLY STONE ENTERPRISE CO., LTD); Manufacturer Part Number: C1210X106K050T
footprint CAP-1210 (1210 (3225M) Capacitor)
pins: 1, 2

## C1210X222K202T
designator C?  Capacitance: 2.2nF  (hidden comment: *)
Capacitor, Ceramic (MLCC), 2.2nF, ±10%, 2kV, X7R, ±10%, SMD 1210; Manufacturer: IHHEC(HOLY STONE ENTERPRISE CO., LTD); Manufacturer Part Number: C1210X222K202T
footprint CAP-1210 (1210 (3225M) Capacitor)
pins: 1, 2

## C1210X222K202TD
designator C?  Capacitance: 2.2nF  (hidden comment: *)
Capacitor, Ceramic (MLCC), 2.2nF, ±10%, 2kV, X7R, ±10%, SMD 1210; Manufacturer: IHHEC(HOLY STONE ENTERPRISE CO., LTD); Manufacturer Part Number: C1210X222K202TD
footprint CAP-1210 (1210 (3225M) Capacitor)
pins: 1, 2

## C1210X223K102T
designator C?  Capacitance: 22nF  (hidden comment: *)
Capacitor, Ceramic (MLCC), 22nF, ±10%, 1kV, X7R, ±10%, SMD 1210; Manufacturer: IHHEC(HOLY STONE ENTERPRISE CO., LTD); Manufacturer Part Number: C1210X223K102T
footprint CAP-1210 (1210 (3225M) Capacitor)
pins: 1, 2

## C1210X223K152TGF
designator C?  Capacitance: 22nF  (hidden comment: *)
Capacitor, Ceramic (MLCC), 22nF, ±10%, 1.5kV, X7R, ±10%, SMD 1210; Manufacturer: IHHEC(HOLY STONE ENTERPRISE CO., LTD); Manufacturer Part Number: C1210X223K152TGF
footprint CAP-1210 (1210 (3225M) Capacitor)
pins: 1, 2

## C1210X223K501T
designator C?  Capacitance: 22nF  (hidden comment: *)
Capacitor, Ceramic (MLCC), 22nF, ±10%, 500V, X7R, ±10%, SMD 1210; Manufacturer: IHHEC(HOLY STONE ENTERPRISE CO., LTD); Manufacturer Part Number: C1210X223K501T
footprint CAP-1210 (1210 (3225M) Capacitor)
pins: 1, 2

## C1210X224K101T
designator C?  Capacitance: 220nF  (hidden comment: *)
Capacitor, Ceramic (MLCC), 220nF, ±10%, 100V, X7R, ±10%, SMD 1210; Manufacturer: IHHEC(HOLY STONE ENTERPRISE CO., LTD); Manufacturer Part Number: C1210X224K101T
footprint CAP-1210 (1210 (3225M) Capacitor)
pins: 1, 2

## C1210X224K251T
designator C?  Capacitance: 220nF  (hidden comment: *)
Capacitor, Ceramic (MLCC), 220nF, ±10%, 250V, X7R, ±10%, SMD 1210; Manufacturer: IHHEC(HOLY STONE ENTERPRISE CO., LTD); Manufacturer Part Number: C1210X224K251T
footprint CAP-1210 (1210 (3225M) Capacitor)
pins: 1, 2

## C1210X225K1RACAUTO
designator C?  Capacitance: 2.2uF  (hidden comment: *)
Capacitor, Ceramic (MLCC), 2.2uF, ±10%, 100V, X7R, ±10%, SMD 1210; Manufacturer: KEMET; Manufacturer Part Number: C1210X225K1RACAUTO
footprint CAP-1210 (1210 (3225M) Capacitor)
pins: 1, 2

## C1210X225K101T
designator C?  Capacitance: 2.2uF  (hidden comment: *)
Capacitor, Ceramic (MLCC), 2.2uF, ±10%, 100V, X7R, ±10%, SMD 1210; Manufacturer: IHHEC(HOLY STONE ENTERPRISE CO., LTD); Manufacturer Part Number: C1210X225K101T
footprint CAP-1210 (1210 (3225M) Capacitor)
pins: 1, 2

## C1210X225K101TF
designator C?  Capacitance: 2.2uF  (hidden comment: *)
Capacitor, Ceramic (MLCC), 2.2uF, ±10%, 100V, X7R, ±10%, SMD 1210; Manufacturer: IHHEC(HOLY STONE ENTERPRISE CO., LTD); Manufacturer Part Number: C1210X225K101TF
footprint CAP-1210 (1210 (3225M) Capacitor)
pins: 1, 2

## C1210X225M101T
designator C?  Capacitance: 2.2uF  (hidden comment: *)
Capacitor, Ceramic (MLCC), 2.2uF, ±20%, 100V, X7R, ±20%, SMD 1210; Manufacturer: IHHEC(HOLY STONE ENTERPRISE CO., LTD); Manufacturer Part Number: C1210X225M101T
footprint CAP-1210 (1210 (3225M) Capacitor)
pins: 1, 2

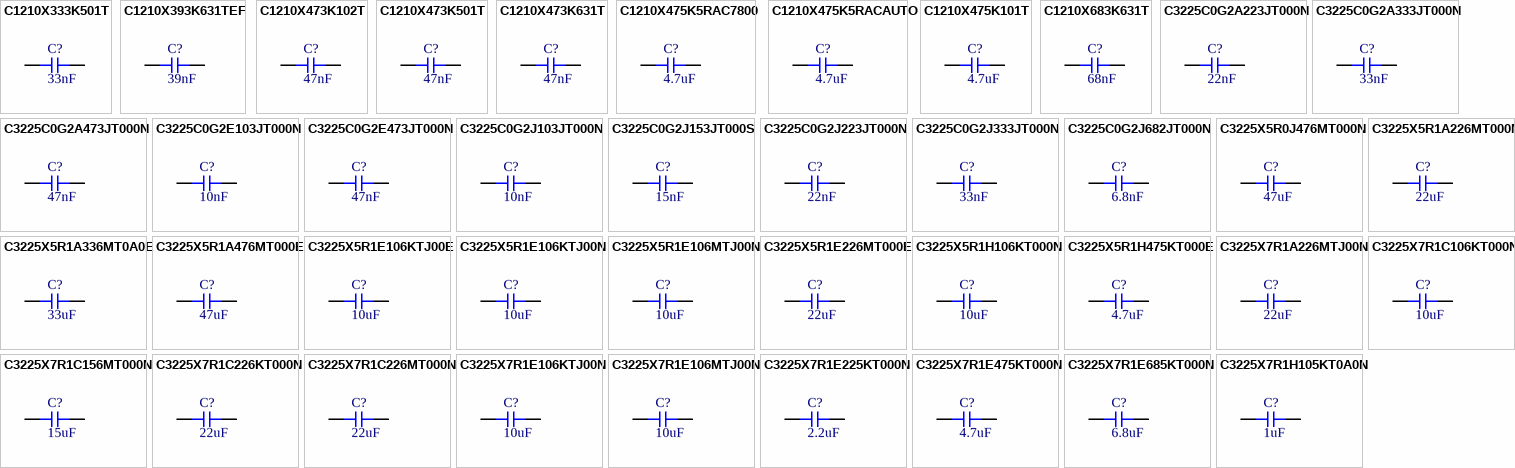
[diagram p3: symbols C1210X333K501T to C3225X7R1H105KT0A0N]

## C1210X333K501T
designator C?  Capacitance: 33nF  (hidden comment: *)
Capacitor, Ceramic (MLCC), 33nF, ±10%, 500V, X7R, ±10%, SMD 1210; Manufacturer: IHHEC(HOLY STONE ENTERPRISE CO., LTD); Manufacturer Part Number: C1210X333K501T
footprint CAP-1210 (1210 (3225M) Capacitor)
pins: 1, 2

## C1210X393K631TEF
designator C?  Capacitance: 39nF  (hidden comment: *)
Capacitor, Ceramic (MLCC), 39nF, ±10%, 630V, X7R, ±10%, SMD 1210; Manufacturer: IHHEC(HOLY STONE ENTERPRISE CO., LTD); Manufacturer Part Number: C1210X393K631TEF
footprint CAP-1210 (1210 (3225M) Capacitor)
pins: 1, 2

## C1210X473K102T
designator C?  Capacitance: 47nF  (hidden comment: *)
Capacitor, Ceramic (MLCC), 47nF, ±10%, 1kV, X7R, ±10%, SMD 1210; Manufacturer: IHHEC(HOLY STONE ENTERPRISE CO., LTD); Manufacturer Part Number: C1210X473K102T
footprint CAP-1210 (1210 (3225M) Capacitor)
pins: 1, 2

## C1210X473K501T
designator C?  Capacitance: 47nF  (hidden comment: *)
Capacitor, Ceramic (MLCC), 47nF, ±10%, 500V, X7R, ±10%, SMD 1210; Manufacturer: IHHEC(HOLY STONE ENTERPRISE CO., LTD); Manufacturer Part Number: C1210X473K501T
footprint CAP-1210 (1210 (3225M) Capacitor)
pins: 1, 2

## C1210X473K631T
designator C?  Capacitance: 47nF  (hidden comment: *)
Capacitor, Ceramic (MLCC), 47nF, ±10%, 630V, X7R, ±10%, SMD 1210; Manufacturer: IHHEC(HOLY STONE ENTERPRISE CO., LTD); Manufacturer Part Number: C1210X473K631T
footprint CAP-1210 (1210 (3225M) Capacitor)
pins: 1, 2

## C1210X475K5RAC7800
designator C?  Capacitance: 4.7uF  (hidden comment: *)
Capacitor, Ceramic (MLCC), 4.7uF, ±10%, 50V, X7R, ±10%, SMD 1210; Manufacturer: KEMET; Manufacturer Part Number: C1210X475K5RAC7800
footprint CAP-1210 (1210 (3225M) Capacitor)
pins: 1, 2

## C1210X475K5RACAUTO
designator C?  Capacitance: 4.7uF  (hidden comment: *)
Capacitor, Ceramic (MLCC), 4.7uF, ±10%, 50V, X7R, ±10%, SMD 1210; Manufacturer: KEMET; Manufacturer Part Number: C1210X475K5RACAUTO
footprint CAP-1210 (1210 (3225M) Capacitor)
pins: 1, 2

## C1210X475K101T
designator C?  Capacitance: 4.7uF  (hidden comment: *)
Capacitor, Ceramic (MLCC), 4.7uF, ±10%, 100V, X7R, ±10%, SMD 1210; Manufacturer: IHHEC(HOLY STONE ENTERPRISE CO., LTD); Manufacturer Part Number: C1210X475K101T
footprint CAP-1210 (1210 (3225M) Capacitor)
pins: 1, 2

## C1210X683K631T
designator C?  Capacitance: 68nF  (hidden comment: *)
Capacitor, Ceramic (MLCC), 68nF, ±10%, 630V, X7R, ±10%, SMD 1210; Manufacturer: IHHEC(HOLY STONE ENTERPRISE CO., LTD); Manufacturer Part Number: C1210X683K631T
footprint CAP-1210 (1210 (3225M) Capacitor)
pins: 1, 2

## C3225C0G2A223JT000N
designator C?  Capacitance: 22nF  (hidden comment: *)
Capacitor, Ceramic (MLCC), 22nF, ±5%, 100V, C0G, ±5%, SMD 1210; Manufacturer: TDK; Manufacturer Part Number: C3225C0G2A223JT000N
footprint CAP-1210 (1210 (3225M) Capacitor)
pins: 1, 2

## C3225C0G2A333JT000N
designator C?  Capacitance: 33nF  (hidden comment: *)
Capacitor, Ceramic (MLCC), 33nF, ±5%, 100V, C0G, ±5%, SMD 1210; Manufacturer: TDK; Manufacturer Part Number: C3225C0G2A333JT000N
footprint CAP-1210 (1210 (3225M) Capacitor)
pins: 1, 2

## C3225C0G2A473JT000N
designator C?  Capacitance: 47nF  (hidden comment: *)
Capacitor, Ceramic (MLCC), 47nF, ±5%, 100V, C0G, ±5%, SMD 1210; Manufacturer: TDK; Manufacturer Part Number: C3225C0G2A473JT000N
footprint CAP-1210 (1210 (3225M) Capacitor)
pins: 1, 2

## C3225C0G2E103JT000N
designator C?  Capacitance: 10nF  (hidden comment: *)
Capacitor, Ceramic (MLCC), 10nF, ±5%, 250V, C0G, ±5%, SMD 1210; Manufacturer: TDK; Manufacturer Part Number: C3225C0G2E103JT000N
footprint CAP-1210 (1210 (3225M) Capacitor)
pins: 1, 2

## C3225C0G2E473JT000N
designator C?  Capacitance: 47nF  (hidden comment: *)
Capacitor, Ceramic (MLCC), 47nF, ±5%, 250V, C0G, ±5%, SMD 1210; Manufacturer: TDK; Manufacturer Part Number: C3225C0G2E473JT000N
footprint CAP-1210 (1210 (3225M) Capacitor)
pins: 1, 2

## C3225C0G2J103JT000N
designator C?  Capacitance: 10nF  (hidden comment: *)
Capacitor, Ceramic (MLCC), 10nF, ±5%, 630V, C0G, ±5%, SMD 1210; Manufacturer: TDK; Manufacturer Part Number: C3225C0G2J103JT000N
footprint CAP-1210 (1210 (3225M) Capacitor)
pins: 1, 2

## C3225C0G2J153JT000S
designator C?  Capacitance: 15nF  (hidden comment: *)
Capacitor, Ceramic (MLCC), 15nF, ±5%, 630V, C0G, ±5%, SMD 1210; Manufacturer: TDK; Manufacturer Part Number: C3225C0G2J153JT000S
footprint CAP-1210 (1210 (3225M) Capacitor)
pins: 1, 2

## C3225C0G2J223JT000N
designator C?  Capacitance: 22nF  (hidden comment: *)
Capacitor, Ceramic (MLCC), 22nF, ±5%, 630V, C0G, ±5%, SMD 1210; Manufacturer: TDK; Manufacturer Part Number: C3225C0G2J223JT000N
footprint CAP-1210 (1210 (3225M) Capacitor)
pins: 1, 2

## C3225C0G2J333JT000N
designator C?  Capacitance: 33nF  (hidden comment: *)
Capacitor, Ceramic (MLCC), 33nF, ±5%, 630V, C0G, ±5%, SMD 1210; Manufacturer: TDK; Manufacturer Part Number: C3225C0G2J333JT000N
footprint CAP-1210 (1210 (3225M) Capacitor)
pins: 1, 2

## C3225C0G2J682JT000N
designator C?  Capacitance: 6.8nF  (hidden comment: *)
Capacitor, Ceramic (MLCC), 6.8nF, ±5%, 630V, C0G, ±5%, SMD 1210; Manufacturer: TDK; Manufacturer Part Number: C3225C0G2J682JT000N
footprint CAP-1210 (1210 (3225M) Capacitor)
pins: 1, 2

## C3225X5R0J476MT000N
designator C?  Capacitance: 47uF  (hidden comment: *)
Capacitor, Ceramic (MLCC), 47uF, ±20%, 6.3V, X5R, ±20%, SMD 1210; Manufacturer: TDK; Manufacturer Part Number: C3225X5R0J476MT000N
footprint CAP-1210 (1210 (3225M) Capacitor)
pins: 1, 2

## C3225X5R1A226MT000N
designator C?  Capacitance: 22uF  (hidden comment: *)
Capacitor, Ceramic (MLCC), 22uF, ±20%, 10V, X5R, ±20%, SMD 1210; Manufacturer: TDK; Manufacturer Part Number: C3225X5R1A226MT000N
footprint CAP-1210 (1210 (3225M) Capacitor)
pins: 1, 2

## C3225X5R1A336MT0A0E
designator C?  Capacitance: 33uF  (hidden comment: *)
Capacitor, Ceramic (MLCC), 33uF, ±20%, 10V, X5R, ±20%, SMD 1210; Manufacturer: TDK; Manufacturer Part Number: C3225X5R1A336MT0A0E
footprint CAP-1210 (1210 (3225M) Capacitor)
pins: 1, 2

## C3225X5R1A476MT000E
designator C?  Capacitance: 47uF  (hidden comment: *)
Capacitor, Ceramic (MLCC), 47uF, ±20%, 10V, X5R, ±20%, SMD 1210; Manufacturer: TDK; Manufacturer Part Number: C3225X5R1A476MT000E
footprint CAP-1210 (1210 (3225M) Capacitor)
pins: 1, 2

## C3225X5R1E106KTJ00E
designator C?  Capacitance: 10uF  (hidden comment: *)
Capacitor, Ceramic (MLCC), 10uF, ±10%, 25V, X5R, ±10%, SMD 1210; Manufacturer: TDK; Manufacturer Part Number: C3225X5R1E106KTJ00E
footprint CAP-1210 (1210 (3225M) Capacitor)
pins: 1, 2

## C3225X5R1E106KTJ00N
designator C?  Capacitance: 10uF  (hidden comment: *)
Capacitor, Ceramic (MLCC), 10uF, ±10%, 25V, X5R, ±10%, SMD 1210; Manufacturer: TDK; Manufacturer Part Number: C3225X5R1E106KTJ00N
footprint CAP-1210 (1210 (3225M) Capacitor)
pins: 1, 2

## C3225X5R1E106MTJ00N
designator C?  Capacitance: 10uF  (hidden comment: *)
Capacitor, Ceramic (MLCC), 10uF, ±20%, 25V, X5R, ±20%, SMD 1210; Manufacturer: TDK; Manufacturer Part Number: C3225X5R1E106MTJ00N
footprint CAP-1210 (1210 (3225M) Capacitor)
pins: 1, 2

## C3225X5R1E226MT000E
designator C?  Capacitance: 22uF  (hidden comment: *)
Capacitor, Ceramic (MLCC), 22uF, ±20%, 25V, X5R, ±20%, SMD 1210; Manufacturer: TDK; Manufacturer Part Number: C3225X5R1E226MT000E
footprint CAP-1210 (1210 (3225M) Capacitor)
pins: 1, 2

## C3225X5R1H106KT000N
designator C?  Capacitance: 10uF  (hidden comment: *)
Capacitor, Ceramic (MLCC), 10uF, ±10%, 50V, X5R, ±10%, SMD 1210; Manufacturer: TDK; Manufacturer Part Number: C3225X5R1H106KT000N
footprint CAP-1210 (1210 (3225M) Capacitor)
pins: 1, 2

## C3225X5R1H475KT000E
designator C?  Capacitance: 4.7uF  (hidden comment: *)
Capacitor, Ceramic (MLCC), 4.7uF, ±10%, 50V, X5R, ±10%, SMD 1210; Manufacturer: TDK; Manufacturer Part Number: C3225X5R1H475KT000E
footprint CAP-1210 (1210 (3225M) Capacitor)
pins: 1, 2

## C3225X7R1A226MTJ00N
designator C?  Capacitance: 22uF  (hidden comment: *)
Capacitor, Ceramic (MLCC), 22uF, ±20%, 10V, X7R, ±20%, SMD 1210; Manufacturer: TDK; Manufacturer Part Number: C3225X7R1A226MTJ00N
footprint CAP-1210 (1210 (3225M) Capacitor)
pins: 1, 2

## C3225X7R1C106KT000N
designator C?  Capacitance: 10uF  (hidden comment: *)
Capacitor, Ceramic (MLCC), 10uF, ±10%, 16V, X7R, ±10%, SMD 1210; Manufacturer: TDK; Manufacturer Part Number: C3225X7R1C106KT000N
footprint CAP-1210 (1210 (3225M) Capacitor)
pins: 1, 2

## C3225X7R1C156MT000N
designator C?  Capacitance: 15uF  (hidden comment: *)
Capacitor, Ceramic (MLCC), 15uF, ±20%, 16V, X7R, ±20%, SMD 1210; Manufacturer: TDK; Manufacturer Part Number: C3225X7R1C156MT000N
footprint CAP-1210 (1210 (3225M) Capacitor)
pins: 1, 2

## C3225X7R1C226KT000N
designator C?  Capacitance: 22uF  (hidden comment: *)
Capacitor, Ceramic (MLCC), 22uF, ±10%, 16V, X7R, ±10%, SMD 1210; Manufacturer: TDK; Manufacturer Part Number: C3225X7R1C226KT000N
footprint CAP-1210 (1210 (3225M) Capacitor)
pins: 1, 2

## C3225X7R1C226MT000N
designator C?  Capacitance: 22uF  (hidden comment: *)
Capacitor, Ceramic (MLCC), 22uF, ±20%, 16V, X7R, ±20%, SMD 1210; Manufacturer: TDK; Manufacturer Part Number: C3225X7R1C226MT000N
footprint CAP-1210 (1210 (3225M) Capacitor)
pins: 1, 2

## C3225X7R1E106KTJ00N
designator C?  Capacitance: 10uF  (hidden comment: *)
Capacitor, Ceramic (MLCC), 10uF, ±10%, 25V, X7R, ±10%, SMD 1210; Manufacturer: TDK; Manufacturer Part Number: C3225X7R1E106KTJ00N
footprint CAP-1210 (1210 (3225M) Capacitor)
pins: 1, 2

## C3225X7R1E106MTJ00N
designator C?  Capacitance: 10uF  (hidden comment: *)
Capacitor, Ceramic (MLCC), 10uF, ±20%, 25V, X7R, ±20%, SMD 1210; Manufacturer: TDK; Manufacturer Part Number: C3225X7R1E106MTJ00N
footprint CAP-1210 (1210 (3225M) Capacitor)
pins: 1, 2

## C3225X7R1E225KT000N
designator C?  Capacitance: 2.2uF  (hidden comment: *)
Capacitor, Ceramic (MLCC), 2.2uF, ±10%, 25V, X7R, ±10%, SMD 1210; Manufacturer: TDK; Manufacturer Part Number: C3225X7R1E225KT000N
footprint CAP-1210 (1210 (3225M) Capacitor)
pins: 1, 2

## C3225X7R1E475KT000N
designator C?  Capacitance: 4.7uF  (hidden comment: *)
Capacitor, Ceramic (MLCC), 4.7uF, ±10%, 25V, X7R, ±10%, SMD 1210; Manufacturer: TDK; Manufacturer Part Number: C3225X7R1E475KT000N
footprint CAP-1210 (1210 (3225M) Capacitor)
pins: 1, 2

## C3225X7R1E685KT000N
designator C?  Capacitance: 6.8uF  (hidden comment: *)
Capacitor, Ceramic (MLCC), 6.8uF, ±10%, 25V, X7R, ±10%, SMD 1210; Manufacturer: TDK; Manufacturer Part Number: C3225X7R1E685KT000N
footprint CAP-1210 (1210 (3225M) Capacitor)
pins: 1, 2

## C3225X7R1H105KT0A0N
designator C?  Capacitance: 1uF  (hidden comment: *)
Capacitor, Ceramic (MLCC), 1uF, ±10%, 50V, X7R, ±10%, SMD 1210; Manufacturer: TDK; Manufacturer Part Number: C3225X7R1H105KT0A0N
footprint CAP-1210 (1210 (3225M) Capacitor)
pins: 1, 2

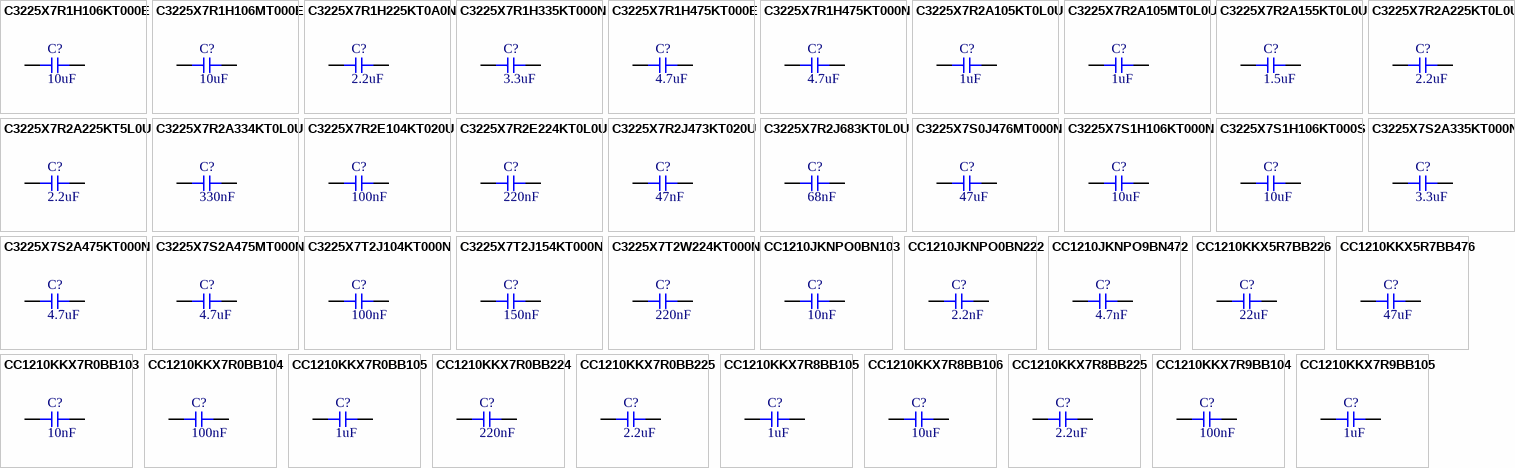
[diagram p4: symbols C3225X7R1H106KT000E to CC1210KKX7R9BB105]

## C3225X7R1H106KT000E
designator C?  Capacitance: 10uF  (hidden comment: *)
Capacitor, Ceramic (MLCC), 10uF, ±10%, 50V, X7R, ±10%, SMD 1210; Manufacturer: TDK; Manufacturer Part Number: C3225X7R1H106KT000E
footprint CAP-1210 (1210 (3225M) Capacitor)
pins: 1, 2

## C3225X7R1H106MT000E
designator C?  Capacitance: 10uF  (hidden comment: *)
Capacitor, Ceramic (MLCC), 10uF, ±20%, 50V, X7R, ±20%, SMD 1210; Manufacturer: TDK; Manufacturer Part Number: C3225X7R1H106MT000E
footprint CAP-1210 (1210 (3225M) Capacitor)
pins: 1, 2

## C3225X7R1H225KT0A0N
designator C?  Capacitance: 2.2uF  (hidden comment: *)
Capacitor, Ceramic (MLCC), 2.2uF, ±10%, 50V, X7R, ±10%, SMD 1210; Manufacturer: TDK; Manufacturer Part Number: C3225X7R1H225KT0A0N
footprint CAP-1210 (1210 (3225M) Capacitor)
pins: 1, 2

## C3225X7R1H335KT000N
designator C?  Capacitance: 3.3uF  (hidden comment: *)
Capacitor, Ceramic (MLCC), 3.3uF, ±10%, 50V, X7R, ±10%, SMD 1210; Manufacturer: TDK; Manufacturer Part Number: C3225X7R1H335KT000N
footprint CAP-1210 (1210 (3225M) Capacitor)
pins: 1, 2

## C3225X7R1H475KT000E
designator C?  Capacitance: 4.7uF  (hidden comment: *)
Capacitor, Ceramic (MLCC), 4.7uF, ±10%, 50V, X7R, ±10%, SMD 1210; Manufacturer: TDK; Manufacturer Part Number: C3225X7R1H475KT000E
footprint CAP-1210 (1210 (3225M) Capacitor)
pins: 1, 2

## C3225X7R1H475KT000N
designator C?  Capacitance: 4.7uF  (hidden comment: *)
Capacitor, Ceramic (MLCC), 4.7uF, ±10%, 50V, X7R, ±10%, SMD 1210; Manufacturer: TDK; Manufacturer Part Number: C3225X7R1H475KT000N
footprint CAP-1210 (1210 (3225M) Capacitor)
pins: 1, 2

## C3225X7R2A105KT0L0U
designator C?  Capacitance: 1uF  (hidden comment: *)
Capacitor, Ceramic (MLCC), 1uF, ±10%, 100V, X7R, ±10%, SMD 1210; Manufacturer: TDK; Manufacturer Part Number: C3225X7R2A105KT0L0U
footprint CAP-1210 (1210 (3225M) Capacitor)
pins: 1, 2

## C3225X7R2A105MT0L0U
designator C?  Capacitance: 1uF  (hidden comment: *)
Capacitor, Ceramic (MLCC), 1uF, ±20%, 100V, X7R, ±20%, SMD 1210; Manufacturer: TDK; Manufacturer Part Number: C3225X7R2A105MT0L0U
footprint CAP-1210 (1210 (3225M) Capacitor)
pins: 1, 2

## C3225X7R2A155KT0L0U
designator C?  Capacitance: 1.5uF  (hidden comment: *)
Capacitor, Ceramic (MLCC), 1.5uF, ±10%, 100V, X7R, ±10%, SMD 1210; Manufacturer: TDK; Manufacturer Part Number: C3225X7R2A155KT0L0U
footprint CAP-1210 (1210 (3225M) Capacitor)
pins: 1, 2

## C3225X7R2A225KT0L0U
designator C?  Capacitance: 2.2uF  (hidden comment: *)
Capacitor, Ceramic (MLCC), 2.2uF, ±10%, 100V, X7R, ±10%, SMD 1210; Manufacturer: TDK; Manufacturer Part Number: C3225X7R2A225KT0L0U
footprint CAP-1210 (1210 (3225M) Capacitor)
pins: 1, 2

## C3225X7R2A225KT5L0U
designator C?  Capacitance: 2.2uF  (hidden comment: *)
Capacitor, Ceramic (MLCC), 2.2uF, ±10%, 100V, X7R, ±10%, SMD 1210; Manufacturer: TDK; Manufacturer Part Number: C3225X7R2A225KT5L0U
footprint CAP-1210 (1210 (3225M) Capacitor)
pins: 1, 2

## C3225X7R2A334KT0L0U
designator C?  Capacitance: 330nF  (hidden comment: *)
Capacitor, Ceramic (MLCC), 330nF, ±10%, 100V, X7R, ±10%, SMD 1210; Manufacturer: TDK; Manufacturer Part Number: C3225X7R2A334KT0L0U
footprint CAP-1210 (1210 (3225M) Capacitor)
pins: 1, 2

## C3225X7R2E104KT020U
designator C?  Capacitance: 100nF  (hidden comment: *)
Capacitor, Ceramic (MLCC), 100nF, ±10%, 250V, X7R, ±10%, SMD 1210; Manufacturer: TDK; Manufacturer Part Number: C3225X7R2E104KT020U
footprint CAP-1210 (1210 (3225M) Capacitor)
pins: 1, 2

## C3225X7R2E224KT0L0U
designator C?  Capacitance: 220nF  (hidden comment: *)
Capacitor, Ceramic (MLCC), 220nF, ±10%, 250V, X7R, ±10%, SMD 1210; Manufacturer: TDK; Manufacturer Part Number: C3225X7R2E224KT0L0U
footprint CAP-1210 (1210 (3225M) Capacitor)
pins: 1, 2

## C3225X7R2J473KT020U
designator C?  Capacitance: 47nF  (hidden comment: *)
Capacitor, Ceramic (MLCC), 47nF, ±10%, 630V, X7R, ±10%, SMD 1210; Manufacturer: TDK; Manufacturer Part Number: C3225X7R2J473KT020U
footprint CAP-1210 (1210 (3225M) Capacitor)
pins: 1, 2

## C3225X7R2J683KT0L0U
designator C?  Capacitance: 68nF  (hidden comment: *)
Capacitor, Ceramic (MLCC), 68nF, ±10%, 630V, X7R, ±10%, SMD 1210; Manufacturer: TDK; Manufacturer Part Number: C3225X7R2J683KT0L0U
footprint CAP-1210 (1210 (3225M) Capacitor)
pins: 1, 2

## C3225X7S0J476MT000N
designator C?  Capacitance: 47uF  (hidden comment: *)
Capacitor, Ceramic (MLCC), 47uF, ±20%, 6.3V, X7S, ±20%, SMD 1210; Manufacturer: TDK; Manufacturer Part Number: C3225X7S0J476MT000N
footprint CAP-1210 (1210 (3225M) Capacitor)
pins: 1, 2

## C3225X7S1H106KT000N
designator C?  Capacitance: 10uF  (hidden comment: *)
Capacitor, Ceramic (MLCC), 10uF, ±10%, 50V, X7S, ±10%, SMD 1210; Manufacturer: TDK; Manufacturer Part Number: C3225X7S1H106KT000N
footprint CAP-1210 (1210 (3225M) Capacitor)
pins: 1, 2

## C3225X7S1H106KT000S
designator C?  Capacitance: 10uF  (hidden comment: *)
Capacitor, Ceramic (MLCC), 10uF, ±10%, 50V, X7S, ±10%, SMD 1210; Manufacturer: TDK; Manufacturer Part Number: C3225X7S1H106KT000S
footprint CAP-1210 (1210 (3225M) Capacitor)
pins: 1, 2

## C3225X7S2A335KT000N
designator C?  Capacitance: 3.3uF  (hidden comment: *)
Capacitor, Ceramic (MLCC), 3.3uF, ±10%, 100V, X7S, ±10%, SMD 1210; Manufacturer: TDK; Manufacturer Part Number: C3225X7S2A335KT000N
footprint CAP-1210 (1210 (3225M) Capacitor)
pins: 1, 2

## C3225X7S2A475KT000N
designator C?  Capacitance: 4.7uF  (hidden comment: *)
Capacitor, Ceramic (MLCC), 4.7uF, ±10%, 100V, X7S, ±10%, SMD 1210; Manufacturer: TDK; Manufacturer Part Number: C3225X7S2A475KT000N
footprint CAP-1210 (1210 (3225M) Capacitor)
pins: 1, 2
